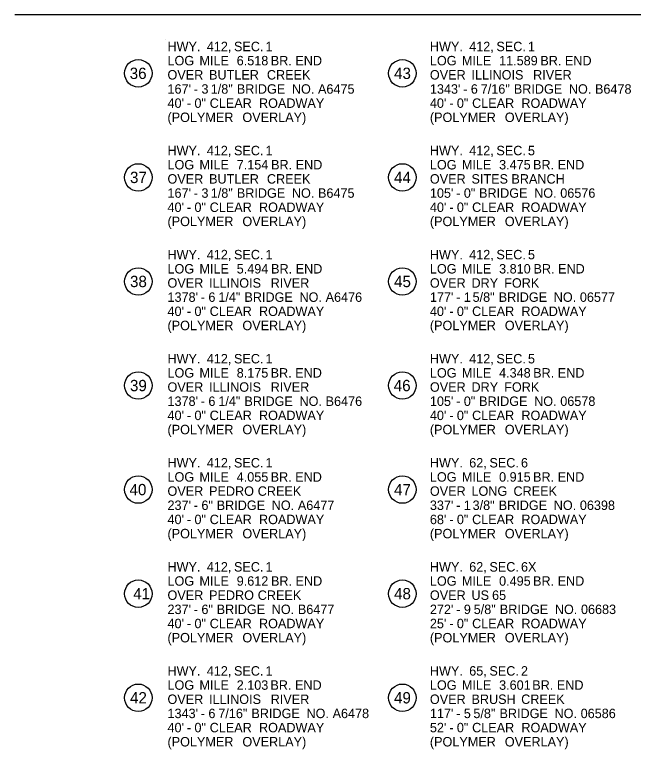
# Model space of a CAD drawing. Extents: x 1930546 to 1934225, y 596452 to 599553.
# Drawn here: x 1932629 to 1933284, y 598586 to 599364 of the extents above; entities that cross this region are included whole.
import ezdxf

# ---------------------------------------------------------------- set-up
doc = ezdxf.new("R2010")
doc.units = 0
doc.layers.add('Default', color=7, linetype='Continuous')
doc.layers.add('R_Border', color=7, linetype='Continuous')

msp = doc.modelspace()

# ---------------------------------------------------------------- linework, layer by layer
at = {"layer": 'R_Border'}
for p, q in [((1934224.56, 599363.54), (1932629.2, 599363.54)), ((1932789.07, 599336.9), (1932789.07, 599336.9))]:
    msp.add_line(p, q, dxfattribs=at)
for centre in [(1932760.13, 599301.47), (1933039.73, 599301.47), (1932760.13, 599191.29), (1933039.73, 599191.29), (1932760.13, 599081.12), (1933039.73, 599081.12), (1932760.13, 598970.94), (1933039.73, 598970.94), (1932760.13, 598860.77), (1933039.73, 598860.77), (1932760.13, 598750.59), (1933039.73, 598750.59), (1932760.13, 598640.42), (1933039.73, 598640.42)]:
    msp.add_circle(centre, 14.52, dxfattribs=at)

# ---------------------------------------------------------------- texts
at = {"layer": 'Default'}
for s, p in [('HWY.', (1932791.02, 599324.9)), (' 412,', (1932828.92, 599324.9)), (' SEC.', (1932857.72, 599324.9)), (' 1', (1932891.13, 599324.9)), ('HWY.', (1933068.89, 599324.9)), (' 412,', (1933106.8, 599324.9)), (' SEC.', (1933135.59, 599324.9)), (' 1', (1933169, 599324.9)), ('LOG', (1932791.02, 599309.9)), (' MILE', (1932821.14, 599309.9)), (' 6.518', (1932860.59, 599309.9)), (' BR.', (1932896.67, 599309.9)), (' END', (1932922.7, 599309.9)), ('LOG', (1933068.89, 599309.9)), (' MILE', (1933099.02, 599309.9)), (' 11.589', (1933138.46, 599309.9)), (' BR.', (1933182.15, 599309.9)), (' END', (1933208.18, 599309.9)), ('OVER', (1932791.02, 599294.9)), (' BUTLER', (1932831.34, 599294.9)), (' CREEK', (1932892.58, 599294.9)), ('OVER', (1933068.89, 599294.9)), (' ILLINOIS', (1933109.22, 599294.9)), (' RIVER', (1933174.47, 599294.9)), ("167'", (1932791.02, 599279.9)), (' -', (1932815.22, 599279.9)), (' 3', (1932823.25, 599279.9)), (' 1/8"', (1932833.09, 599279.9)), (' BRIDGE', (1932860.72, 599279.9)), (' NO.', (1932919.04, 599279.9)), (' A6475', (1932946.7, 599279.9)), ("1343'", (1933068.89, 599279.9)), (' -', (1933100.48, 599279.9)), (' 6', (1933108.51, 599279.9)), (' 7/16"', (1933119.02, 599279.9)), (' BRIDGE', (1933154.04, 599279.9)), (' NO.', (1933212.35, 599279.9)), (' B6478', (1933240.01, 599279.9)), ("40'", (1932791.02, 599264.9)), (' -', (1932807.83, 599264.9)), (' 0"', (1932815.86, 599264.9)), (' CLEAR', (1932831.99, 599264.9)), (' ROADWAY', (1932884.21, 599264.9)), ("40'", (1933068.89, 599264.9)), (' -', (1933085.7, 599264.9)), (' 0"', (1933093.73, 599264.9)), (' CLEAR', (1933109.87, 599264.9)), (' ROADWAY', (1933162.09, 599264.9)), ('(POLYMER', (1932791.02, 599249.9)), (' OVERLAY)', (1932866.62, 599249.9)), ('(POLYMER', (1933068.89, 599249.9)), (' OVERLAY)', (1933144.5, 599249.9)), ('HWY.', (1932791.02, 599214.72)), (' 412,', (1932828.92, 599214.72)), (' SEC.', (1932857.72, 599214.72)), (' 1', (1932891.13, 599214.72)), ('HWY.', (1933068.89, 599214.72)), (' 412,', (1933106.8, 599214.72)), (' SEC.', (1933135.59, 599214.72)), (' 5', (1933169, 599214.72)), ('LOG', (1932791.02, 599199.72)), (' MILE', (1932821.14, 599199.72)), (' 7.154', (1932860.59, 599199.72)), (' BR.', (1932897.01, 599199.72)), (' END', (1932923.04, 599199.72)), ('LOG', (1933068.89, 599199.72)), (' MILE', (1933099.02, 599199.72)), (' 3.475', (1933138.46, 599199.72)), (' BR.', (1933174.42, 599199.72)), (' END', (1933200.45, 599199.72)), ('OVER', (1932791.02, 599184.72)), (' BUTLER', (1932831.34, 599184.72)), (' CREEK', (1932892.58, 599184.72)), ('OVER', (1933068.89, 599184.72)), (' SITES', (1933109.22, 599184.72)), (' BRANCH', (1933151.51, 599184.72)), ("167'", (1932791.02, 599169.72)), (' 3', (1932823.25, 599169.72)), (' 1/8"', (1932833.09, 599169.72)), (' BRIDGE', (1932860.72, 599169.72)), (' NO.', (1932919.04, 599169.72)), (' B6475', (1932946.7, 599169.72)), ("105'", (1933068.89, 599169.72)), (' 0"', (1933101.12, 599169.72)), (' BRIDGE', (1933117.25, 599169.72)), (' NO.', (1933175.57, 599169.72)), (' 06576', (1933203.23, 599169.72)), (' -', (1932815.22, 599169.72)), (' -', (1933093.09, 599169.72)), ("40'", (1932791.02, 599154.72)), (' 0"', (1932815.86, 599154.72)), (' CLEAR', (1932831.99, 599154.72)), (' ROADWAY', (1932884.21, 599154.72)), ("40'", (1933068.89, 599154.72)), (' 0"', (1933093.73, 599154.72)), (' CLEAR', (1933109.87, 599154.72)), (' ROADWAY', (1933162.09, 599154.72)), (' -', (1932807.83, 599154.72)), (' -', (1933085.7, 599154.72)), ('(POLYMER', (1932791.02, 599139.72)), (' OVERLAY)', (1932866.62, 599139.72)), ('(POLYMER', (1933068.89, 599139.72)), (' OVERLAY)', (1933144.5, 599139.72)), ('HWY.', (1932791.02, 599104.55)), (' 412,', (1932828.92, 599104.55)), (' SEC.', (1932857.72, 599104.55)), (' 1', (1932891.13, 599104.55)), ('HWY.', (1933068.89, 599104.55)), (' 412,', (1933106.8, 599104.55)), (' SEC.', (1933135.59, 599104.55)), (' 5', (1933169, 599104.55)), ('LOG', (1932791.02, 599089.55)), (' MILE', (1932821.14, 599089.55)), (' 5.494', (1932860.59, 599089.55)), (' BR.', (1932897.01, 599089.55)), (' END', (1932923.04, 599089.55)), ('LOG', (1933068.89, 599089.55)), (' MILE', (1933099.02, 599089.55)), (' 3.810', (1933138.46, 599089.55)), (' BR.', (1933174.87, 599089.55)), (' END', (1933200.9, 599089.55)), ('OVER', (1932791.02, 599074.55)), (' ILLINOIS', (1932831.34, 599074.55)), (' RIVER', (1932896.59, 599074.55)), ('OVER', (1933068.89, 599074.55)), (' DRY', (1933109.22, 599074.55)), (' FORK', (1933143.88, 599074.55)), ("1378'", (1932791.02, 599059.55)), (' 6', (1932830.63, 599059.55)), (' 1/4"', (1932841.14, 599059.55)), (' BRIDGE', (1932868.77, 599059.55)), (' NO.', (1932927.09, 599059.55)), (' A6476', (1932954.75, 599059.55)), ("177'", (1933068.89, 599059.55)), (' 1', (1933101.12, 599059.55)), (' 5/8"', (1933110.39, 599059.55)), (' BRIDGE', (1933138.01, 599059.55)), (' NO.', (1933196.33, 599059.55)), (' 06577', (1933223.99, 599059.55)), (' -', (1932822.61, 599059.55)), (' -', (1933093.09, 599059.55)), ("40'", (1932791.02, 599044.55)), (' 0"', (1932815.86, 599044.55)), (' CLEAR', (1932831.99, 599044.55)), (' ROADWAY', (1932884.21, 599044.55)), ("40'", (1933068.89, 599044.55)), (' 0"', (1933093.73, 599044.55)), (' CLEAR', (1933109.87, 599044.55)), (' ROADWAY', (1933162.09, 599044.55)), (' -', (1932807.83, 599044.55)), (' -', (1933085.7, 599044.55)), ('(POLYMER', (1932791.02, 599029.55)), (' OVERLAY)', (1932866.62, 599029.55)), ('(POLYMER', (1933068.89, 599029.55)), (' OVERLAY)', (1933144.5, 599029.55)), ('HWY.', (1932791.02, 598994.37)), (' 412,', (1932828.92, 598994.37)), (' SEC.', (1932857.72, 598994.37)), (' 1', (1932891.13, 598994.37)), ('HWY.', (1933068.89, 598994.37)), (' 412,', (1933106.8, 598994.37)), (' SEC.', (1933135.59, 598994.37)), (' 5', (1933169, 598994.37)), ('LOG', (1932791.02, 598979.37)), (' MILE', (1932821.14, 598979.37)), (' 8.175', (1932860.59, 598979.37)), (' BR.', (1932896.54, 598979.37)), (' END', (1932922.57, 598979.37)), ('LOG', (1933068.89, 598979.37)), (' MILE', (1933099.02, 598979.37)), (' 4.348', (1933138.46, 598979.37)), (' BR.', (1933174.55, 598979.37)), (' END', (1933200.58, 598979.37)), ('OVER', (1932791.02, 598964.37)), (' ILLINOIS', (1932831.34, 598964.37)), (' RIVER', (1932896.59, 598964.37)), ('OVER', (1933068.89, 598964.37)), (' DRY', (1933109.22, 598964.37)), (' FORK', (1933143.88, 598964.37)), ("1378'", (1932791.02, 598949.37)), (' 6', (1932830.63, 598949.37)), (' 1/4"', (1932841.14, 598949.37)), (' BRIDGE', (1932868.77, 598949.37)), (' NO.', (1932927.09, 598949.37)), (' B6476', (1932954.75, 598949.37)), ("105'", (1933068.89, 598949.37)), (' 0"', (1933101.12, 598949.37)), (' BRIDGE', (1933117.25, 598949.37)), (' NO.', (1933175.57, 598949.37)), (' 06578', (1933203.23, 598949.37)), (' -', (1932822.61, 598949.37)), (' -', (1933093.09, 598949.37)), ("40'", (1932791.02, 598934.37)), (' 0"', (1932815.86, 598934.37)), (' CLEAR', (1932831.99, 598934.37)), (' ROADWAY', (1932884.21, 598934.37)), ("40'", (1933068.89, 598934.37)), (' 0"', (1933093.73, 598934.37)), (' CLEAR', (1933109.87, 598934.37)), (' ROADWAY', (1933162.09, 598934.37)), (' -', (1932807.83, 598934.37)), (' -', (1933085.7, 598934.37)), ('(POLYMER', (1932791.02, 598919.37)), (' OVERLAY)', (1932866.62, 598919.37)), ('(POLYMER', (1933068.89, 598919.37)), (' OVERLAY)', (1933144.5, 598919.37)), ('HWY.', (1932791.02, 598884.2)), (' 412,', (1932828.92, 598884.2)), (' SEC.', (1932857.72, 598884.2)), (' 1', (1932891.13, 598884.2)), ('HWY.', (1933068.89, 598884.2)), (' 62,', (1933106.8, 598884.2)), (' SEC.', (1933128.2, 598884.2)), (' 6', (1933161.62, 598884.2)), ('LOG', (1932791.02, 598869.2)), (' 4.055', (1932860.59, 598869.2)), ('LOG', (1933068.89, 598869.2)), (' 0.915', (1933138.46, 598869.2)), (' MILE', (1932821.14, 598869.2)), (' BR.', (1932896.54, 598869.2)), (' END', (1932922.57, 598869.2)), (' MILE', (1933099.02, 598869.2)), (' BR.', (1933174.42, 598869.2)), (' END', (1933200.45, 598869.2)), ('OVER', (1932791.02, 598854.2)), (' PEDRO', (1932831.34, 598854.2)), (' CREEK', (1932882.87, 598854.2)), ('OVER', (1933068.89, 598854.2)), (' LONG', (1933109.22, 598854.2)), (' CREEK', (1933153.7, 598854.2)), ("237'", (1932791.02, 598839.2)), (' 6"', (1932823.25, 598839.2)), (' BRIDGE', (1932839.38, 598839.2)), (' NO.', (1932897.69, 598839.2)), (' A6477', (1932925.35, 598839.2)), ("337'", (1933068.89, 598839.2)), (' 1', (1933101.12, 598839.2)), (' 3/8"', (1933110.39, 598839.2)), (' BRIDGE', (1933138.01, 598839.2)), (' NO.', (1933196.33, 598839.2)), (' 06398', (1933223.99, 598839.2)), (' -', (1932815.22, 598839.2)), (' -', (1933093.09, 598839.2)), ("40'", (1932791.02, 598824.2)), (' 0"', (1932815.86, 598824.2)), (' CLEAR', (1932831.99, 598824.2)), (' ROADWAY', (1932884.21, 598824.2)), ("68'", (1933068.89, 598824.2)), (' 0"', (1933093.73, 598824.2)), (' CLEAR', (1933109.87, 598824.2)), (' ROADWAY', (1933162.09, 598824.2)), (' -', (1932807.83, 598824.2)), (' -', (1933085.7, 598824.2)), ('(POLYMER', (1932791.02, 598809.2)), (' OVERLAY)', (1932866.62, 598809.2)), ('(POLYMER', (1933068.89, 598809.2)), (' OVERLAY)', (1933144.5, 598809.2)), ('HWY.', (1932791.02, 598774.02)), (' 412,', (1932828.92, 598774.02)), (' SEC.', (1932857.72, 598774.02)), (' 1', (1932891.13, 598774.02)), ('HWY.', (1933068.89, 598774.02)), (' 62,', (1933106.8, 598774.02)), (' SEC.', (1933128.2, 598774.02)), (' 6X', (1933161.62, 598774.02)), ('LOG', (1932791.02, 598759.02)), (' MILE', (1932821.14, 598759.02)), (' 9.612', (1932860.59, 598759.02)), (' BR.', (1932896.9, 598759.02)), (' END', (1932922.93, 598759.02)), ('LOG', (1933068.89, 598759.02)), (' MILE', (1933099.02, 598759.02)), (' 0.495', (1933138.46, 598759.02)), (' BR.', (1933174.42, 598759.02)), (' END', (1933200.45, 598759.02)), ('OVER', (1932791.02, 598744.02)), (' PEDRO', (1932831.34, 598744.02)), (' CREEK', (1932882.87, 598744.02)), ('OVER', (1933068.89, 598744.02)), (' US', (1933109.22, 598744.02)), (' 65', (1933131.01, 598744.02)), (' 5/8"', (1933111.57, 598729.02)), ("237'", (1932791.02, 598729.02)), (' -', (1932815.22, 598729.02)), (' 6"', (1932823.25, 598729.02)), (' BRIDGE', (1932839.38, 598729.02)), (' NO.', (1932897.69, 598729.02)), (' B6477', (1932925.35, 598729.02)), ("272'", (1933068.89, 598729.02)), (' -', (1933093.09, 598729.02)), (' 9', (1933101.12, 598729.02)), (' BRIDGE', (1933139.2, 598729.02)), (' NO.', (1933197.51, 598729.02)), (' 06683', (1933225.17, 598729.02)), ("40'", (1932791.02, 598714.02)), (' 0"', (1932815.86, 598714.02)), (' CLEAR', (1932831.99, 598714.02)), (' ROADWAY', (1932884.21, 598714.02)), ("25'", (1933068.89, 598714.02)), (' 0"', (1933093.73, 598714.02)), (' CLEAR', (1933109.87, 598714.02)), (' ROADWAY', (1933162.09, 598714.02)), (' -', (1932807.83, 598714.02)), (' -', (1933085.7, 598714.02)), ('(POLYMER', (1932791.02, 598699.02)), (' OVERLAY)', (1932866.62, 598699.02)), ('(POLYMER', (1933068.89, 598699.02)), (' OVERLAY)', (1933144.5, 598699.02)), ('HWY.', (1932791.02, 598663.85)), (' 412,', (1932828.92, 598663.85)), (' SEC.', (1932857.72, 598663.85)), (' 1', (1932891.13, 598663.85)), ('HWY.', (1933068.89, 598663.85)), (' 65,', (1933106.8, 598663.85)), (' SEC.', (1933128.2, 598663.85)), (' 2', (1933161.62, 598663.85)), ('LOG', (1932791.02, 598648.85)), (' MILE', (1932821.14, 598648.85)), (' 2.103', (1932860.59, 598648.85)), (' BR.', (1932896.29, 598648.85)), (' END', (1932922.32, 598648.85)), ('LOG', (1933068.89, 598648.85)), (' MILE', (1933099.02, 598648.85)), (' 3.601', (1933138.46, 598648.85)), (' BR.', (1933173.58, 598648.85)), (' END', (1933199.61, 598648.85)), ('OVER', (1932791.02, 598633.85)), (' ILLINOIS', (1932831.34, 598633.85)), (' RIVER', (1932896.59, 598633.85)), ('OVER', (1933068.89, 598633.85)), (' BRUSH', (1933109.22, 598633.85)), (' CREEK', (1933161.84, 598633.85)), ("1343'", (1932791.02, 598618.85)), (' -', (1932822.61, 598618.85)), (' 6', (1932830.63, 598618.85)), (' 7/16"', (1932841.14, 598618.85)), (' BRIDGE', (1932876.16, 598618.85)), (' NO.', (1932934.48, 598618.85)), (' A6478', (1932962.13, 598618.85)), ("117'", (1933068.89, 598618.85)), (' -', (1933093.09, 598618.85)), (' 5', (1933101.12, 598618.85)), (' 5/8"', (1933111.22, 598618.85)), (' BRIDGE', (1933138.85, 598618.85)), (' NO.', (1933197.17, 598618.85)), (' 06586', (1933224.83, 598618.85)), ("40'", (1932791.02, 598603.85)), (' -', (1932807.83, 598603.85)), (' 0"', (1932815.86, 598603.85)), (' CLEAR', (1932831.99, 598603.85)), (' ROADWAY', (1932884.21, 598603.85)), ("52'", (1933068.89, 598603.85)), (' -', (1933085.7, 598603.85)), (' 0"', (1933093.73, 598603.85)), (' CLEAR', (1933109.87, 598603.85)), (' ROADWAY', (1933162.09, 598603.85)), ('(POLYMER', (1932791.02, 598588.85)), (' OVERLAY)', (1932866.62, 598588.85)), ('(POLYMER', (1933068.89, 598588.85)), (' OVERLAY)', (1933144.5, 598588.85))]:
    msp.add_text(s, height=10, dxfattribs=at).set_placement(p)
at = {"layer": 'R_Border'}
for s, p in [('36', (1932751.01, 599295.47)), ('43', (1933030.95, 599295.47)), ('37', (1932751.34, 599185.29)), ('44', (1933030.95, 599185.29)), ('38', (1932751.34, 599075.12)), ('45', (1933030.95, 599075.12)), ('39', (1932751.29, 598964.94)), ('46', (1933030.62, 598964.94)), ('40', (1932750.82, 598854.77)), ('47', (1933030.95, 598854.77)), ('41', (1932754.74, 598744.59)), ('48', (1933030.95, 598744.59)), ('42', (1932751.34, 598634.42)), ('49', (1933030.9, 598634.42))]:
    msp.add_text(s, height=12, rotation=360, dxfattribs=at).set_placement(p)

doc.saveas('drawing.dxf')
